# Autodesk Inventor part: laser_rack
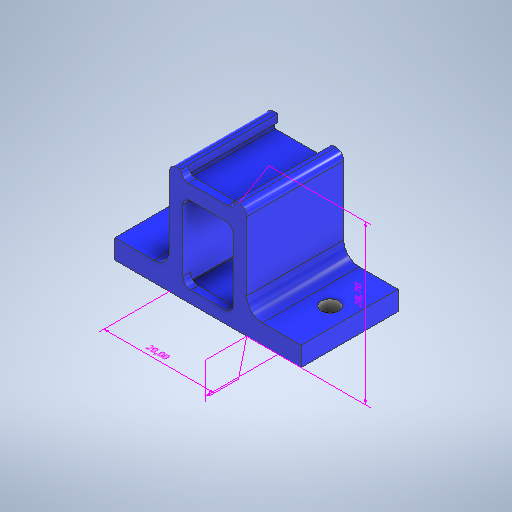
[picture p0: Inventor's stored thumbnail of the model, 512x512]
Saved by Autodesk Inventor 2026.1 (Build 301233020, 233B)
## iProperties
Created: 2026-10
Part Number: laser_rack
Material: Generic
Document SubType Name: Modeling
Designer: alolo
Density: 1 g/cm^3
Appearance: Default
Author: alolo
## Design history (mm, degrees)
node "Annotations"
  node "Linear Dimension 1" dims "d4" = 1.7, "d28" = 25 (derived)
  node "Linear Dimension 2" dims "d4" = 1.7, "d30" = 28.7 (derived)
  node "Linear Dimension 3" dims "d4" = 1.7, "d33" = 20 (derived)
sketch "Sketch1"
  geometry: L1 (0, 0)-(20, 0); L2 (20, 0)-(20, 26.7); L3 (0, 26.7)-(0, 0); L4 (20, 33.282)-(20, 31.582); L5 (17.75, 25)-(2.25, 25); L6 (0, 31.582)-(0, 33.282); L7 (3, 26.7)-(3, 28.7); L8 (17, 26.7)-(17, 28.7); L9 (2, 28.7)-(3, 28.7); L10 (2.25, 26.7)-(3, 26.7); L11 (17, 26.7)-(17.75, 26.7); L12 (17, 28.7)-(18, 28.7); L13 (17.75, 26.7)-(17.75, 25); L14 (17.75, 25)-(2.25, 25); L15 (2.25, 25)-(2.25, 26.7); L16 (17.75, 1.4)-(10, 1.4); L17 (17.75, 1.4)-(10, 1.4); L18 (16.5, 3.1)-(17.75, 3.1); L19 (17.75, 3.1)-(17.75, 1.4); L20 (16.5, 23)-(10, 23); L21 (10, 0)-(10, 25); L22 (16.5, 3.1)-(16.5, 23); L23 (3.5, 3.1)-(3.5, 23); L24 (3.5, 23)-(10, 23); L25 (2.25, 3.1)-(2.25, 1.4); L26 (2.25, 1.4)-(10, 1.4); L27 (3.5, 3.1)-(2.25, 3.1); A1 r 2 centre (2, 26.7) between (2, 28.7) and (0, 26.7); A2 r 2 centre (18, 26.7) between (20, 26.7) and (18, 28.7); 4 further points
  constraints: 54 end point, 9 perpendicular, 8 point on line, 6 parallel, 5 horizontal, 4 midpoint, 4 point on circle, 4 symmetric about line, 4 tangent, 2 centre point, 2 collinear, 2 vertical, 1 coincident, 1 equal radius, 1 vertical alignment
  dimensions: "d7" = 28.7 distance of L1.end point (20, 28.7) (computed from d37); "d8" = 3 distance between parallel lines of L3 L7; "d9" = 3 distance between parallel lines of L2 L8; "d10" = 15.5 distance of L5.start L5.end; "d15" = 1.4 distance between parallel lines of L16 L1; "d16" = 2 distance between parallel lines of L5 L20; "d21" = 7.75 distance of L16.start L16.end; "d22" = 6.5 distance of L20.start L20.end; "d34" = 20 distance of L1.start L1.end; "d35" = 3.1 distance between parallel lines of L1 L27; "d37" = 25 distance between parallel lines of L1 L5; "d38" = 0.75 distance of L8.start L11.end; "d39" = 2 distance between parallel lines of L10 L9; "d40" = 2 radius of A1; "d41" = 2 radius of A2 (derived); "d42" = 1.7 distance of L5.end L10.start; "d43" = 1.7 distance of L11.end L5.start; "d44" = 1.7 distance of L25.start L25.end
extrude "Extrusion1" new body sketch "Sketch1" distance "d11" = 25; taper "d12" = 0 deg
sketch "Sketch3"
  geometry: L1 (2.25, 1.4)-(2.25, 3.1) reference; L2 (17.75, 3.1)-(17.75, 1.4) reference; L3 (2.25, 3.1)-(17.75, 3.1); L4 (17.75, 3.1)-(17.75, 1.4); L5 (17.75, 1.4)-(2.25, 1.4); L6 (2.25, 1.4)-(2.25, 3.1); L7 (2.25, 26.7)-(3, 26.7) reference; L8 (17.75, 25)-(2.25, 25) reference; L9 (2.25, 26.7)-(17.75, 26.7); L10 (17.75, 26.7)-(17.75, 25); L11 (17.75, 25)-(2.25, 25); L12 (2.25, 25)-(2.25, 26.7); 5 further points
  constraints: 16 end point, 4 parallel, 2 horizontal, 2 perpendicular
extrude "Extrusion3" join sketch "Sketch3" distance "d23" = 2; taper "d24" = 0 deg
fillet "Fillet3" dims "d25" = 2
sketch "Sketch4"
  geometry: L1 (0, 0)-(-14, 0); L2 (-14, 0)-(-14, 5); L3 (-14, 5)-(0, 5); L4 (0, 5)-(0, 0); L5 (0, 0)-(20, 0) reference; L6 (10, 0)-(10, 26.7); L7 (5, 26.7)-(15, 26.7) reference; L8 (34, 5)-(20, 5); L9 (34, 0)-(34, 5); L10 (20, 0)-(34, 0); L11 (20, 5)-(20, 0)
  constraints: 18 end point, 3 symmetric about line, 2 midpoint, 2 parallel, 1 horizontal, 1 perpendicular
  dimensions: "d45" = 14 distance of L2.end L3.end; "d46" = 5 distance of L1.end L2.end
extrude "Extrusion4" join sketch "Sketch4" stored distance "d47" = 10; taper "d48" = 0 deg
fillet "Fillet4" dims "d49" = 4
sketch "Sketch5"
  geometry: L1 (-10, 0)-(-10, 25) reference; L2 (0, 0)-(-10, 0) reference; L3 (0, 0)-(0, 25) reference; L4 (-10, 25)-(0, 25) reference; L5 (-38, 25)-(-38, 0) reference; L6 (-48, 25)-(-38, 25) reference; L7 (-48, 0)-(-48, 25) reference; L8 (-38, 0)-(-48, 0) reference; C1 r 1 at (-5, 12.5); C2 r 1 at (-43, 12.5); 5 further points
  constraints: 4 midpoint, 2 centre point, 2 horizontal alignment, 2 vertical alignment
  dimensions: "d50" = 2 diameter of C1; "d51" = 2 diameter of C2
extrude "Extrusion5" cut sketch "Sketch5" stored distance "d52" = 10; taper "d53" = 0 deg
sketch "Sketch6"
  geometry: 4 further points
hole "Hole1" sketch "Sketch6" at (-5, 12.5), (-43, 12.5), (-5, -112.5), (-43, -112.5) diameter "d54" = 4.5; stored, may be unused: countersink angle "d58" = 90 deg, drill point angle "d60" = 0 deg; dims "d55" = 6, "d56" = 4, "d57" = 2, "d59" = 8
body "Solid1"
feature "խ耀ծ耀կ耀հ耀ձ耀ղ耀ճ耀մ耀"
node "Projected Loop1"
node "Projected Loop2"
other parameters: "d6" = 2, "d26" = 0 (derived), "d29" = 7.96182 (derived), "d31" = 0 (derived)
